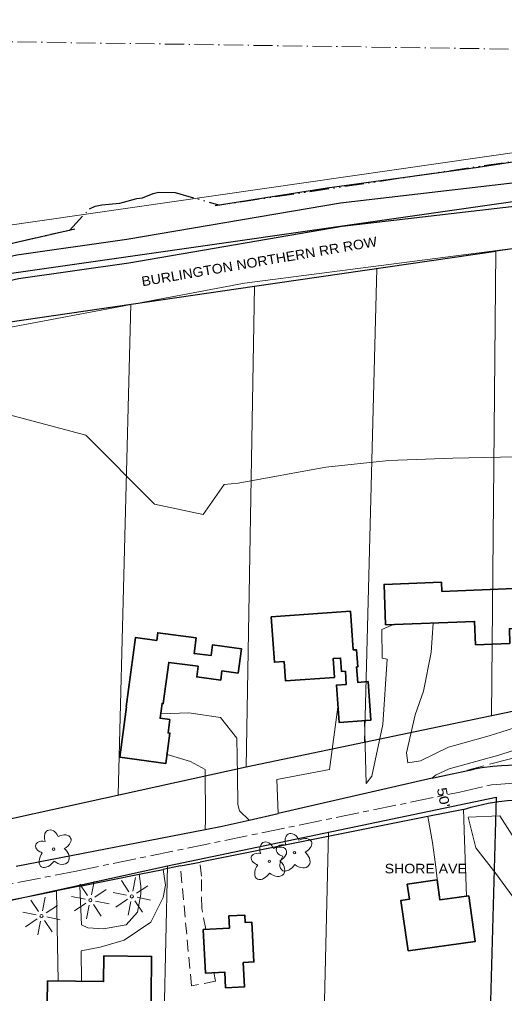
# Model space of a CAD drawing. Extents: x -861682 to -858969, y -1797841 to -1795153.
# Drawn here: x -860654 to -860350, y -1795768 to -1795158 of the extents above; entities that cross this region are included whole.
import ezdxf

# ---------------------------------------------------------------- set-up
doc = ezdxf.new("R2010")
doc.units = 0
doc.header["$LTSCALE"] = 2.4
for name, pattern in [('DASH_DOUBLE_DOT', [9.2, 5, -1.2, 0.3, -1.2, 0.3, -1.2]), ('DOT_DASHED', [7.7, 5, -1.2, 0.3, -1.2]), ('LONG_DASH_SHORT_DASH', [9.9, 6, -1.2, 1.5, -1.2]), ('LONG_DASHED', [7.5, 6, -1.5]), ('MEDIUM_DASHED', [4.5, 3, -1.5])]:
    doc.linetypes.add(name, pattern=pattern)
for name, color, linetype, lineweight in [('10', 7, 'Continuous', 25), ('11', 7, 'Continuous', 13), ('12', 7, 'Continuous', 35), ('14', 7, 'Continuous', 25), ('16', 7, 'DASH_DOUBLE_DOT', 25), ('17', 7, 'Continuous', 13), ('18', 7, 'Continuous', 13), ('30', 7, 'Continuous', 13), ('32', 7, 'LONG_DASH_SHORT_DASH', 13), ('42', 7, 'Continuous', 25), ('46', 7, 'Continuous', 13), ('52', 7, 'LONG_DASHED', 13), ('6', 7, 'Continuous', 25), ('61', 7, 'Continuous', 13)]:
    doc.layers.add(name, color=color, linetype=linetype, lineweight=lineweight)
doc.layers.add('43', color=7, linetype='Continuous')

msp = doc.modelspace()

# ---------------------------------------------------------------- linework, layer by layer
at = {"layer": '10'}
for p, q in [((-860395.171, -1795632.712), (-860491.564, -1795654.772)), ((-860397.934, -1795656.751), (-860540.602, -1795685.274)), ((-860375.595, -1795652.285), (-860397.934, -1795656.751)), ((-860655.702, -1795687.948), (-860537.314, -1795664.883)), ((-860552.915, -1795687.736), (-860563.624, -1795689.878)), ((-860552.915, -1795687.736), (-860540.602, -1795685.274)), ((-860615.896, -1795700.33), (-860578.634, -1795692.879)), ((-860578.634, -1795692.879), (-860563.624, -1795689.878)), ((-860615.896, -1795700.33), (-860630.452, -1795703.241))]:
    msp.add_line(p, q, dxfattribs=at)
for points in [[(-860395.171, -1795632.712), (-860392.548, -1795632.112), (-860368.961, -1795627.179)], [(-860269.159, -1795645.097), (-860273.302, -1795642.507), (-860283.128, -1795637.523), (-860294.347, -1795632.943), (-860303.791, -1795629.921), (-860314.504, -1795627.348), (-860322.106, -1795626.047), (-860328.671, -1795625.263), (-860333.065, -1795624.911), (-860338.569, -1795624.664), (-860341.875, -1795624.619), (-860344.079, -1795624.631), (-860347.383, -1795624.715), (-860351.785, -1795624.946), (-860357.274, -1795625.428), (-860364.036, -1795626.319), (-860368.961, -1795627.179)], [(-860375.595, -1795652.285), (-860370.813, -1795650.823), (-860360.031, -1795648.305), (-860353.5, -1795647.281), (-860348.02, -1795646.706), (-860343.621, -1795646.428), (-860340.317, -1795646.326), (-860338.113, -1795646.309), (-860334.807, -1795646.36), (-860330.405, -1795646.57), (-860323.823, -1795647.189), (-860316.201, -1795648.37), (-860304.422, -1795651.213), (-860294.014, -1795654.821), (-860283.982, -1795659.373), (-860272.561, -1795666.026), (-860261.946, -1795673.9), (-860253.033, -1795682.108), (-860244.998, -1795691.178), (-860237.331, -1795701.944), (-860231.882, -1795711.519)], [(-860537.314, -1795664.883), (-860526.732, -1795662.822), (-860509.77, -1795658.939), (-860491.564, -1795654.772)], [(-860703.253, -1795717.798), (-860683.051, -1795713.758), (-860630.452, -1795703.241)]]:
    msp.add_lwpolyline(points, dxfattribs=at)
at = {"layer": '11'}
msp.add_line((-860629.517, -1795759.791), (-860630.452, -1795703.241), dxfattribs=at)
for points in [[(-860394.54, -1795535.544), (-860395.83, -1795553.928), (-860400.58, -1795578.308), (-860405.886, -1795593.004), (-860411.348, -1795616.918), (-860410.349, -1795623.053), (-860402.563, -1795621.803), (-860384.914, -1795613.379), (-860359.456, -1795606.304), (-860323.875, -1795594.887), (-860314.194, -1795594.093), (-860314.037, -1795612.05), (-860315.687, -1795612.537), (-860336.714, -1795612.957), (-860353.444, -1795618.301), (-860384.56, -1795626.844), (-860393.031, -1795630.935), (-860395.171, -1795632.712)], [(-860419.387, -1795536.498), (-860426.674, -1795539.547), (-860426.518, -1795557.504), (-860423.44, -1795558.186), (-860426.154, -1795599.089), (-860432.96, -1795631.521), (-860436.465, -1795636.041), (-860437.576, -1795596.709)], [(-860454.198, -1795588.212), (-860459.462, -1795627.263), (-860492.489, -1795633.459), (-860491.564, -1795654.772)], [(-860565.244, -1795592.489), (-860547.673, -1795591.881), (-860527.799, -1795594.779), (-860517.525, -1795607.685), (-860517.085, -1795631.075), (-860516.926, -1795649.268), (-860515.945, -1795653.276), (-860509.77, -1795658.939)], [(-860561.178, -1795617.811), (-860546.461, -1795622.352), (-860537.44, -1795627.235), (-860537.163, -1795658.897), (-860537.314, -1795664.883)], [(-860397.934, -1795656.751), (-860395.027, -1795673.013), (-860393.017, -1795686.7), (-860390.988, -1795704.649)], [(-860375.595, -1795652.285), (-860375.307, -1795658.19), (-860375.243, -1795665.515), (-860373.73, -1795706.648)], [(-860615.896, -1795700.33), (-860614.803, -1795724.556), (-860610.77, -1795726.411), (-860601.076, -1795727.036), (-860586.92, -1795724.549), (-860579.664, -1795716.688), (-860577.636, -1795705.328), (-860577.68, -1795700.366), (-860578.634, -1795692.879)], [(-860614.84, -1795759.958), (-860615.133, -1795740.864), (-860603.101, -1795738.632), (-860588.017, -1795734.247), (-860571.338, -1795722.995), (-860563.675, -1795707.569), (-860562.326, -1795699.759), (-860563.624, -1795689.878)]]:
    msp.add_lwpolyline(points, dxfattribs=at)
at = {"layer": '11', "linetype": 'MEDIUM_DASHED'}
for points in [[(-860531.872, -1795754.552), (-860530.845, -1795759.976), (-860545.944, -1795762.707), (-860552.915, -1795687.736)], [(-860537.026, -1795727.348), (-860539.515, -1795714.21), (-860539.691, -1795694.127), (-860540.602, -1795685.274)]]:
    msp.add_lwpolyline(points, dxfattribs=at)
at = {"layer": '12'}
for points in [[(-860424.337, -1795536.689), (-860368.59, -1795534.548), (-860368.028, -1795549.18), (-860346.45, -1795548.351), (-860346.806, -1795539.091), (-860326.014, -1795538.292), (-860326.934, -1795514.356), (-860343.748, -1795515.002), (-860343.787, -1795513.998), (-860389.128, -1795515.759), (-860389.354, -1795509.933), (-860425.32, -1795511.328)], [(-860495.978, -1795531.645), (-860446.387, -1795528.14), (-860444.673, -1795552.386), (-860442.615, -1795552.241), (-860441.855, -1795563.03), (-860442.522, -1795563.077), (-860441.842, -1795572.723), (-860435.323, -1795572.263), (-860433.618, -1795596.43), (-860453.519, -1795597.834), (-860455.168, -1795574.456), (-860448.998, -1795574.021), (-860449.58, -1795565.767), (-860451.954, -1795565.934), (-860452.545, -1795557.526), (-860457.257, -1795557.857), (-860456.434, -1795569.58), (-860487.136, -1795571.735), (-860487.978, -1795559.741), (-860493.974, -1795560.162)], [(-860590.909, -1795619.667), (-860586.696, -1795587.966), (-860586.794, -1795587.953), (-860581.059, -1795544.719), (-860567.722, -1795546.488), (-860567.079, -1795541.642), (-860542.989, -1795544.838), (-860544.276, -1795554.542), (-860533.721, -1795555.942), (-860532.839, -1795549.295), (-860514.711, -1795551.7), (-860516.732, -1795566.931), (-860526.889, -1795565.583), (-860527.648, -1795571.299), (-860542.66, -1795569.306), (-860541.778, -1795562.662), (-860560.223, -1795560.213), (-860563.646, -1795585.994), (-860564.37, -1795585.898), (-860565.6, -1795595.177), (-860559.517, -1795595.983), (-860560.624, -1795604.34), (-860559.411, -1795604.501), (-860561.935, -1795623.513)], [(-860410.265, -1795740.962), (-860414.794, -1795709.338), (-860409.491, -1795708.578), (-860410.844, -1795699.14), (-860392.162, -1795696.462), (-860390.36, -1795709.032), (-860372.273, -1795706.439), (-860368.188, -1795734.929)], [(-860538.691, -1795727.434), (-860537.27, -1795754.832), (-860525.115, -1795754.202), (-860524.608, -1795763.975), (-860512.735, -1795763.359), (-860513.521, -1795748.216), (-860506.811, -1795747.868), (-860508.104, -1795722.928), (-860512.306, -1795723.146), (-860512.549, -1795718.453), (-860522.605, -1795718.974), (-860522.211, -1795726.58)], [(-860636.235, -1795759.714), (-860601.024, -1795760.115), (-860600.841, -1795744.028), (-860570.928, -1795744.368), (-860571.507, -1795795.28), (-860592.912, -1795795.037), (-860592.837, -1795788.406), (-860636.554, -1795787.912)]]:
    msp.add_lwpolyline(points, close=True, dxfattribs=at)
at = {"layer": '14'}
for points in [[(-860285.168, -1795237.757), (-860366.345, -1795250.28), (-860460.986, -1795263.158), (-860531.07, -1795274.167)], [(-860619.079, -1795288.878), (-860685.581, -1795304.109), (-860745.955, -1795317.633), (-860828.478, -1795338.202), (-860875.885, -1795348.306)]]:
    msp.add_lwpolyline(points, dxfattribs=at)
at = {"layer": '16'}
for points in [[(-860285.168, -1795237.757), (-860528.26, -1795273.819)], [(-860622.283, -1795289.612), (-860609.739, -1795276.037), (-860606.21, -1795274.352), (-860602.199, -1795273.608), (-860590.866, -1795272.564), (-860580.259, -1795269.636), (-860576.718, -1795269.132), (-860569.889, -1795266.473), (-860566.587, -1795265.736), (-860556.189, -1795265.881), (-860528.26, -1795273.819)], [(-860622.283, -1795289.612), (-860685.581, -1795304.109), (-860745.955, -1795317.633), (-860828.478, -1795338.202), (-860877.038, -1795348.552)]]:
    msp.add_lwpolyline(points, dxfattribs=at)
at = {"layer": '17'}
for p, q in [((-860611.066, -1795706.248), (-860615.856, -1795699.12)), ((-860608.606, -1795705.788), (-860606.88, -1795697.388)), ((-860585.095, -1795703.894), (-860589.885, -1795696.766)), ((-860582.635, -1795703.434), (-860580.909, -1795695.034)), ((-860580.435, -1795704.834), (-860573.339, -1795700.094)), ((-860606.406, -1795707.188), (-860599.31, -1795702.448)), ((-860586.595, -1795706.094), (-860595.057, -1795704.42)), ((-860641.698, -1795716.204), (-860646.488, -1795709.076)), ((-860639.238, -1795715.744), (-860637.512, -1795707.344)), ((-860637.038, -1795717.144), (-860629.942, -1795712.404)), ((-860612.566, -1795708.448), (-860621.028, -1795706.774)), ((-860612.026, -1795710.948), (-860619.252, -1795715.804)), ((-860611.646, -1795720.908), (-860609.966, -1795712.308)), ((-860607.306, -1795711.848), (-860602.506, -1795719.062)), ((-860605.966, -1795709.708), (-860597.486, -1795711.432)), ((-860586.055, -1795708.594), (-860593.281, -1795713.45)), ((-860585.675, -1795718.554), (-860583.995, -1795709.954)), ((-860581.335, -1795709.494), (-860576.535, -1795716.708)), ((-860579.995, -1795707.354), (-860571.515, -1795709.078)), ((-860643.198, -1795718.404), (-860651.66, -1795716.73)), ((-860642.658, -1795720.904), (-860649.884, -1795725.76)), ((-860642.278, -1795730.864), (-860640.598, -1795722.264)), ((-860637.938, -1795721.804), (-860633.138, -1795729.018)), ((-860636.598, -1795719.664), (-860628.118, -1795721.388))]:
    msp.add_line(p, q, dxfattribs=at)
for points in [[(-860632.05, -1795684.625), (-860631.008, -1795685.393), (-860629.602, -1795686.115), (-860628.354, -1795686.521), (-860626.982, -1795686.717), (-860625.964, -1795686.667), (-860624.82, -1795686.377), (-860623.888, -1795685.825), (-860623.148, -1795685.037), (-860622.68, -1795684.079), (-860622.47, -1795683.001), (-860622.574, -1795681.805), (-860622.864, -1795680.633), (-860623.35, -1795679.573), (-860624.072, -1795678.429), (-860624.938, -1795677.509), (-860625.62, -1795676.897), (-860624.438, -1795676.181), (-860623.292, -1795675.233), (-860622.372, -1795674.141), (-860621.85, -1795673.285), (-860621.518, -1795672.471), (-860621.372, -1795671.655), (-860621.412, -1795670.893), (-860621.628, -1795670.213), (-860621.886, -1795669.761), (-860622.306, -1795669.287), (-860622.766, -1795668.933), (-860623.332, -1795668.643), (-860624.568, -1795668.315), (-860625.81, -1795668.281), (-860627.856, -1795668.657), (-860629.516, -1795669.295), (-860630.306, -1795667.717), (-860630.96, -1795666.903), (-860631.372, -1795666.501), (-860631.836, -1795666.101), (-860632.438, -1795665.709), (-860633.442, -1795665.277), (-860634.456, -1795665.107), (-860635.344, -1795665.207), (-860636.144, -1795665.541), (-860636.81, -1795666.027), (-860637.37, -1795666.733), (-860637.72, -1795667.489), (-860637.878, -1795667.927), (-860638.046, -1795668.603), (-860638.098, -1795669.765), (-860638.026, -1795670.663), (-860637.814, -1795671.625), (-860637.53, -1795672.431), (-860638.972, -1795672.199), (-860640.33, -1795672.249), (-860641.488, -1795672.535), (-860642.376, -1795673.033), (-860642.816, -1795673.377), (-860643.25, -1795673.943), (-860643.488, -1795674.477), (-860643.612, -1795675.155), (-860643.41, -1795676.259), (-860642.954, -1795677.071), (-860642.33, -1795677.833), (-860641.552, -1795678.449), (-860640.854, -1795678.873), (-860640.19, -1795679.161), (-860639.462, -1795679.399), (-860640.146, -1795680.611), (-860640.768, -1795681.979), (-860641.164, -1795683.481), (-860641.298, -1795684.815), (-860641.288, -1795685.905), (-860640.954, -1795686.923), (-860640.432, -1795687.769), (-860639.874, -1795688.205), (-860639.488, -1795688.451), (-860638.754, -1795688.675), (-860637.96, -1795688.687), (-860637.19, -1795688.563), (-860636.53, -1795688.351), (-860635.786, -1795688.029), (-860634.71, -1795687.349), (-860633.748, -1795686.563), (-860632.792, -1795685.545), (-860632.046, -1795684.635)], [(-860481.274, -1795686.852), (-860480.232, -1795687.62), (-860478.826, -1795688.342), (-860477.578, -1795688.748), (-860476.206, -1795688.944), (-860475.188, -1795688.894), (-860474.044, -1795688.604), (-860473.112, -1795688.052), (-860472.372, -1795687.264), (-860471.904, -1795686.306), (-860471.694, -1795685.228), (-860471.798, -1795684.032), (-860472.088, -1795682.86), (-860472.574, -1795681.8), (-860473.296, -1795680.656), (-860474.162, -1795679.736), (-860474.844, -1795679.124), (-860473.662, -1795678.408), (-860472.516, -1795677.46), (-860471.596, -1795676.368), (-860471.074, -1795675.512), (-860470.742, -1795674.698), (-860470.596, -1795673.882), (-860470.636, -1795673.12), (-860470.852, -1795672.44), (-860471.11, -1795671.988), (-860471.53, -1795671.514), (-860471.99, -1795671.16), (-860472.556, -1795670.87), (-860473.792, -1795670.542), (-860475.034, -1795670.508), (-860477.08, -1795670.884), (-860478.74, -1795671.522), (-860479.53, -1795669.944), (-860480.184, -1795669.13), (-860480.596, -1795668.728), (-860481.06, -1795668.328), (-860481.662, -1795667.936), (-860482.666, -1795667.504), (-860483.68, -1795667.334), (-860484.568, -1795667.434), (-860485.368, -1795667.768), (-860486.034, -1795668.254), (-860486.594, -1795668.96), (-860486.944, -1795669.716), (-860487.102, -1795670.154), (-860487.27, -1795670.83), (-860487.322, -1795671.992), (-860487.25, -1795672.89), (-860487.038, -1795673.852), (-860486.754, -1795674.658), (-860488.196, -1795674.426), (-860489.554, -1795674.476), (-860490.712, -1795674.762), (-860491.6, -1795675.26), (-860492.04, -1795675.604), (-860492.474, -1795676.17), (-860492.712, -1795676.704), (-860492.836, -1795677.382), (-860492.634, -1795678.486), (-860492.178, -1795679.298), (-860491.554, -1795680.06), (-860490.776, -1795680.676), (-860490.078, -1795681.1), (-860489.414, -1795681.388), (-860488.686, -1795681.626), (-860489.37, -1795682.838), (-860489.992, -1795684.206), (-860490.388, -1795685.708), (-860490.522, -1795687.042), (-860490.512, -1795688.132), (-860490.178, -1795689.15), (-860489.656, -1795689.996), (-860489.098, -1795690.432), (-860488.712, -1795690.678), (-860487.978, -1795690.902), (-860487.184, -1795690.914), (-860486.414, -1795690.79), (-860485.754, -1795690.578), (-860485.01, -1795690.256), (-860483.934, -1795689.576), (-860482.972, -1795688.79), (-860482.016, -1795687.772), (-860481.27, -1795686.862)], [(-860497.059, -1795692.188), (-860496.017, -1795692.956), (-860494.611, -1795693.678), (-860493.363, -1795694.084), (-860491.991, -1795694.28), (-860490.973, -1795694.23), (-860489.829, -1795693.94), (-860488.897, -1795693.388), (-860488.157, -1795692.6), (-860487.689, -1795691.642), (-860487.479, -1795690.564), (-860487.583, -1795689.368), (-860487.873, -1795688.196), (-860488.359, -1795687.136), (-860489.081, -1795685.992), (-860489.947, -1795685.072), (-860490.629, -1795684.46), (-860489.447, -1795683.744), (-860488.301, -1795682.796), (-860487.381, -1795681.704), (-860486.859, -1795680.848), (-860486.527, -1795680.034), (-860486.381, -1795679.218), (-860486.421, -1795678.456), (-860486.637, -1795677.776), (-860486.895, -1795677.324), (-860487.315, -1795676.85), (-860487.775, -1795676.496), (-860488.341, -1795676.206), (-860489.577, -1795675.878), (-860490.819, -1795675.844), (-860492.865, -1795676.22), (-860494.525, -1795676.858), (-860495.315, -1795675.28), (-860495.969, -1795674.466), (-860496.381, -1795674.064), (-860496.845, -1795673.664), (-860497.447, -1795673.272), (-860498.451, -1795672.84), (-860499.465, -1795672.67), (-860500.353, -1795672.77), (-860501.153, -1795673.104), (-860501.819, -1795673.59), (-860502.379, -1795674.296), (-860502.729, -1795675.052), (-860502.887, -1795675.49), (-860503.055, -1795676.166), (-860503.107, -1795677.328), (-860503.035, -1795678.226), (-860502.823, -1795679.188), (-860502.539, -1795679.994), (-860503.981, -1795679.762), (-860505.339, -1795679.812), (-860506.497, -1795680.098), (-860507.385, -1795680.596), (-860507.825, -1795680.94), (-860508.259, -1795681.506), (-860508.497, -1795682.04), (-860508.621, -1795682.718), (-860508.419, -1795683.822), (-860507.963, -1795684.634), (-860507.339, -1795685.396), (-860506.561, -1795686.012), (-860505.863, -1795686.436), (-860505.199, -1795686.724), (-860504.471, -1795686.962), (-860505.155, -1795688.174), (-860505.777, -1795689.542), (-860506.173, -1795691.044), (-860506.307, -1795692.378), (-860506.297, -1795693.468), (-860505.963, -1795694.486), (-860505.441, -1795695.332), (-860504.883, -1795695.768), (-860504.497, -1795696.014), (-860503.763, -1795696.238), (-860502.969, -1795696.25), (-860502.199, -1795696.126), (-860501.539, -1795695.914), (-860500.795, -1795695.592), (-860499.719, -1795694.912), (-860498.757, -1795694.126), (-860497.801, -1795693.108), (-860497.055, -1795692.198)]]:
    msp.add_lwpolyline(points, dxfattribs=at)
for centre, radius in [((-860632.23, -1795677.213), 0.773), ((-860481.454, -1795679.44), 0.773), ((-860497.239, -1795684.776), 0.773), ((-860583.295, -1795706.794), 1), ((-860609.266, -1795709.148), 1), ((-860639.898, -1795719.104), 1)]:
    msp.add_circle(centre, radius, dxfattribs=at)
at = {"layer": '18'}
for points in [[(-861627.784, -1795676.931), (-861596.674, -1795662.729), (-861531.982, -1795629.555), (-861487.69, -1795614.518), (-861432.082, -1795596.546), (-861364.083, -1795563.344), (-861330.912, -1795546.255), (-861278.234, -1795519.917), (-861241.977, -1795502.494), (-861200.029, -1795489.604), (-861135.894, -1795473.921), (-861059.793, -1795448.445), (-860986.512, -1795424.884), (-860905.443, -1795400.073), (-860827.906, -1795376.712), (-860758.776, -1795364.765), (-860677.115, -1795353.655), (-860512.688, -1795322.681), (-860272.176, -1795291.516), (-860031.805, -1795256.984)], [(-860332.63, -1795431.213), (-860382.242, -1795432.355), (-860422.401, -1795433.651), (-860461.824, -1795438.013), (-860516.794, -1795447.945), (-860525.53, -1795448.73), (-860538.599, -1795467.511), (-860569.136, -1795461.162), (-860612.048, -1795417.822), (-860670.31, -1795402.5), (-860717.5, -1795410.473), (-860764.397, -1795424.825), (-860811.58, -1795433.507), (-860833.927, -1795445.045), (-860882.481, -1795459.174), (-860948.091, -1795468.254), (-860994.524, -1795481.656)], [(-860336.505, -1795718.104), (-860355.396, -1795692.512), (-860367.824, -1795676.317), (-860372.717, -1795657.22), (-860352.876, -1795656.337), (-860337.305, -1795680.54)]]:
    msp.add_lwpolyline(points, dxfattribs=at)
at = {"layer": '30'}
for p, q in [((-859934.264, -1795182.08), (-860691.022, -1795290.795)), ((-860358.065, -1795593.541), (-860355.24, -1795302.654)), ((-860437.582, -1795610.141), (-860429.955, -1795313.437)), ((-860511.736, -1795625.621), (-860506.554, -1795324.492)), ((-860591.858, -1795643.192), (-860583.956, -1795335.81)), ((-860460.096, -1795666.586), (-860464.207, -1795843.408)), ((-860560.934, -1795687.607), (-860564.854, -1795869.105))]:
    msp.add_line(p, q, dxfattribs=at)
at = {"layer": '32'}
msp.add_lwpolyline([(-861635.972, -1796031.868), (-861610.028, -1796010.347), (-861588.712, -1795995.544), (-861565.619, -1795981.925), (-861538.381, -1795968.898), (-861510.551, -1795957.055), (-861477.984, -1795945.213), (-861420.547, -1795924.488), (-861317.516, -1795885.408), (-861160.601, -1795826.787), (-861110.862, -1795807.247), (-861056.978, -1795788.298), (-861002.502, -1795772.311), (-860944.474, -1795756.916), (-860841.147, -1795735.302), (-860618.21, -1795690.893), (-860377.808, -1795641.449), (-860358.046, -1795636.933), (-860342.059, -1795635.749), (-860328.736, -1795636.637), (-860314.229, -1795638.413), (-860299.425, -1795641.966), (-860286.694, -1795646.999), (-860274.26, -1795653.513)], dxfattribs=at)
at = {"layer": '42'}
for p, q in [((-859737.4, -1795184.957), (-860685.181, -1795320.287)), ((-860045.907, -1795258.409), (-860355.24, -1795302.654)), ((-860506.554, -1795324.492), (-860355.24, -1795302.654)), ((-860660.89, -1795347.059), (-860506.554, -1795324.492)), ((-860511.736, -1795625.621), (-860320.225, -1795585.642)), ((-860667.521, -1795659.786), (-860511.736, -1795625.621)), ((-860658.826, -1795709.196), (-860560.934, -1795687.607))]:
    msp.add_line(p, q, dxfattribs=at)
msp.add_lwpolyline([(-860560.934, -1795687.607), (-860355.195, -1795644.718), (-860359.939, -1795817.565)], dxfattribs=at)
at = {"layer": '52'}
msp.add_lwpolyline([(-860327.93, -1795617.605), (-860345.392, -1795620.357), (-860372.975, -1795627.688)], dxfattribs=at)
at = {"layer": '6'}
for points in [[(-861626.979, -1795642.068), (-861544.533, -1795599.421), (-861437.181, -1795553.823), (-861360.226, -1795517.943), (-861269.063, -1795485.483), (-861201.703, -1795460.32), (-861135.053, -1795434.926), (-860930.273, -1795370.755), (-860759.796, -1795329.096), (-860655.328, -1795305.026), (-860586.415, -1795295.208), (-860452.636, -1795272.3), (-860334.137, -1795258.505), (-859981.661, -1795225.976)], [(-861627.338, -1795657.588), (-861543.402, -1795614.17), (-861436.05, -1795568.572), (-861359.095, -1795532.692), (-861267.932, -1795500.232), (-861200.572, -1795475.069), (-861133.922, -1795449.675), (-860929.142, -1795385.504), (-860758.665, -1795343.845), (-860654.197, -1795319.775), (-860585.284, -1795309.957), (-860451.505, -1795287.049), (-860333.006, -1795273.254), (-859980.53, -1795240.725)]]:
    msp.add_lwpolyline(points, dxfattribs=at)
at = {"layer": '61', "linetype": 'DOT_DASHED'}
msp.add_line((-861615.801, -1795157.51), (-858974.429, -1795196.105), dxfattribs=at)

# ---------------------------------------------------------------- texts
at = {"layer": '43', "width": 1.2}
msp.add_text("50'", height=6, rotation=281.427, dxfattribs=at).set_placement((-860392.278, -1795639.282))
at = {"layer": '46', "width": 1.1}
msp.add_text('SHORE AVE', height=6, dxfattribs=at).set_placement((-860424.937, -1795692.362))
at = {"layer": '6', "width": 1.1}
msp.add_text('BURLINGTON NORTHERN RR ROW', height=6, rotation=9.713, dxfattribs=at).set_placement((-860576.677, -1795324.662))

doc.saveas('drawing.dxf')
